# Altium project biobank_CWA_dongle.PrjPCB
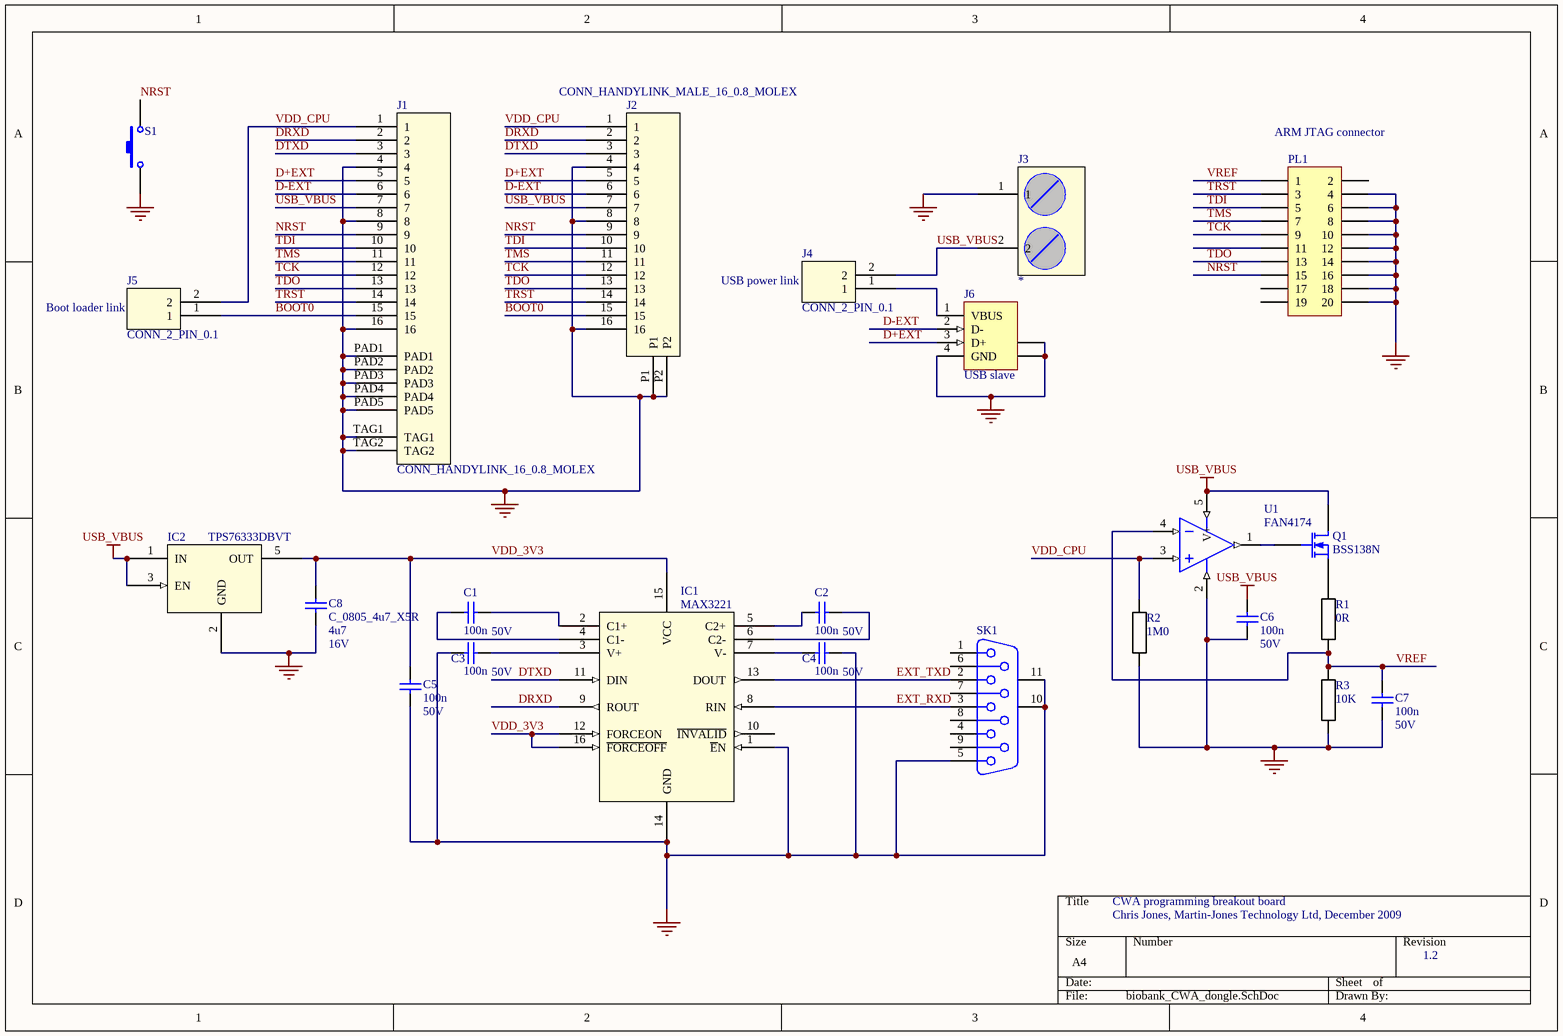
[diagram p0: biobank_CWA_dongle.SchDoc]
1 sheet, 24 parts. Net scope: global (net labels, ports and power ports of the same name join across sheets).
Board file: biobank_CWA_dongle.PcbDoc

## Sheet biobank_CWA_dongle.SchDoc
size A4; PageSetup: Record=PageOptions|SelectedOnly=False|CenterHorizontal=True|CenterVertical=True|PrintScale=1.00|XCorrection=1.00|YCorrection=1.00|PrintKind=0|BorderSize=5000000|LeftOffset=0|BottomOffset=0|Orientation=2|PaperLength=1000|PaperWidth=1000|Scale=100|PaperSource=7|PrintQuality=-4|MediaType=1|DitherType=10|PaperKind=A4|PrintScaleMode=1

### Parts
C1  value 100n  V: 50V  [0805-NP]
C2  value 100n  V: 50V  [0805-NP]
C3  value 100n  V: 50V  [0805-NP]
C4  value 100n  V: 50V  [0805-NP]
C5  value 100n  V: 50V  [0805-NP]
C6  value 100n  V: 50V  [0805-NP]
C7  value 100n  V: 50V  [0805-NP]
C8  C_0805_4u7_X5R  value 4u7  V: 16V  [0805-NP]
IC1  MAX3221  [SSO-G16/X.45]
IC2  TPS76333DBVT  [SOT23-5]
J1  CONN_HANDYLINK_16_0.8_MOLEX  [HANDYLINK_16]
J2  CONN_HANDYLINK_MALE_16_0.8_MOLEX  [MOLEX_4559316xx]
J3  *  [2WAY_5MM_TERMINAL]
J4  CONN_2_PIN_0.1  [2WAY_0.1]
J5  CONN_2_PIN_0.1  [2WAY_0.1]
J6  USB slave  [USB_B]
PL1  (no value)  [HDR2X10]
Q1  BSS138N  [SOT23-3]
R1  R: 0R  [CR2012-0805]  (hidden comment: R_0R_0805_1_MULTICOMP)
R2  R: 1M0  [CR2012-0805]  (hidden comment: R_1M0_0805_1_MULTICOMP_1)
R3  R: 10K  [CR2012-0805]  (hidden comment: R_10K_0805_1_MULTICOMP)
S1  (no value)  [OMRON_B3U_B]
SK1  (no value)  [DSUB1.385-2H9]
U1  FAN4174  [SOT23-5]

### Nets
GND: C3.1 C4.2 C5.2 C6.1 C7.1 C8.1 IC1.1(~{E}N) IC1.14(GND) IC2.2(GND) J1.4 J1.8 J1.16 J1.PAD1 J1.PAD2 J1.PAD3 J1.PAD4 J1.PAD5 J1.TAG1 J1.TAG2 J2.4 J2.8 J2.16 J2.P1 J2.P2 J3.1 J6.4(GND) J6.5(SHLD) J6.6(SHLD) PL1.4 PL1.6 PL1.8 PL1.10 PL1.12 PL1.14 PL1.16 PL1.18 PL1.20 R2.1 R3.1 S1.1 SK1.5 SK1.10(MH1) SK1.11(MH2) U1.2(V-)
USB_VBUS: C6.2 IC2.1(IN) IC2.3(EN) J1.7 J2.7 J3.2 J4.2 Q1.1(D) U1.5(V+)
BOOT0: J1.15 J2.15 J5.1
D+EXT: J1.5 J2.5 J6.3(D+)
D-EXT: J1.6 J2.6 J6.2(D-)
DRXD: IC1.9(ROUT) J1.2 J2.2
DTXD: IC1.11(DIN) J1.3 J2.3
EXT_RXD: IC1.8(RIN) SK1.3
EXT_TXD: IC1.13(DOUT) SK1.2
NRST: J1.9 J2.9 PL1.15 S1.2
TCK: J1.12 J2.12 PL1.9
TDI: J1.10 J2.10 PL1.5
TDO: J1.13 J2.13 PL1.13
TMS: J1.11 J2.11 PL1.7
TRST: J1.14 J2.14 PL1.3
VDD_3V3: C5.1 C8.2 IC1.12(FORCEON) IC1.15(VCC) IC1.16(~{FORCEOFF}) IC2.5(OUT)
VDD_CPU: J1.1 J2.1 J5.2 R2.2 U1.3(IN+)
VREF: C7.2 PL1.1 R1.1 R3.2 U1.4(IN-)
NetC1_1: C1.1 IC1.4(C1-)
NetC1_2: C1.2 IC1.2(C1+)
NetC2_1: C2.1 IC1.5(C2+)
NetC2_2: C2.2 IC1.6(C2-)
NetC3_2: C3.2 IC1.3(V+)
NetC4_1: C4.1 IC1.7(V-)
NetJ4_1: J4.1 J6.1(VBUS)
NetQ1_2: Q1.2(G) U1.1(OUT)
NetQ1_3: Q1.3(S) R1.2

Not connected (* = marked no-connect by the designer): IC1 10(~{INVALID}); PL1 2 11 17 19; SK1 1 4 6 7 8 9

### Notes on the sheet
- (near PL1) ARM JTAG connector
- (near J5) Boot loader link
- USB power link
- CWA programming breakout board
- Chris Jones, Martin-Jones Technology Ltd, December 2009
- 1.2

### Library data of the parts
C1-C7 = C_0805_100n_X7R: Capacitor
C8 = C_0805_4u7_X5R: Capacitor
IC1 = MAX3221CDBE4: RS232 transceiver; Manufacturer: Maxim
J1 = CONN_HANDYLINK_16_0.8_MOLEX: Molex Handylink 16 way 0.8mm Female; MOLEX: 448281162
J2 = CONN_HANDYLINK_MALE_16_0.8_MOLEX: Molex Handylink 16 way 0.8mm male; MOLEX: 455931600
J3 = CONN_2_PIN_5MM_TERM: 2 way 5mm screw terminal
J4 = CONN_2_PIN_0.1: 2 pin 0.1in header
J6 = CONN_USB_SLAVE: USB Slave connector
PL1 = CONN_10X2: Header, 10-Pin, Dual row
Q1 = BSS138N: N-Channel MOSFET; pin to pad: 1>3 2>1 3>2
R3 = R_10K_0805_1_MULTICOMP: MJT: 10019
S1 = SW-NO-OMRON-B3U-1000P-B: Switch
SK1 = CONN_DB9_FEMALE: Receptacle Assembly, 9 Position, Right Angle; Package Information: Latest Revision: O; Positions: 9
U1 = FAN4174: Operational Amplifier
